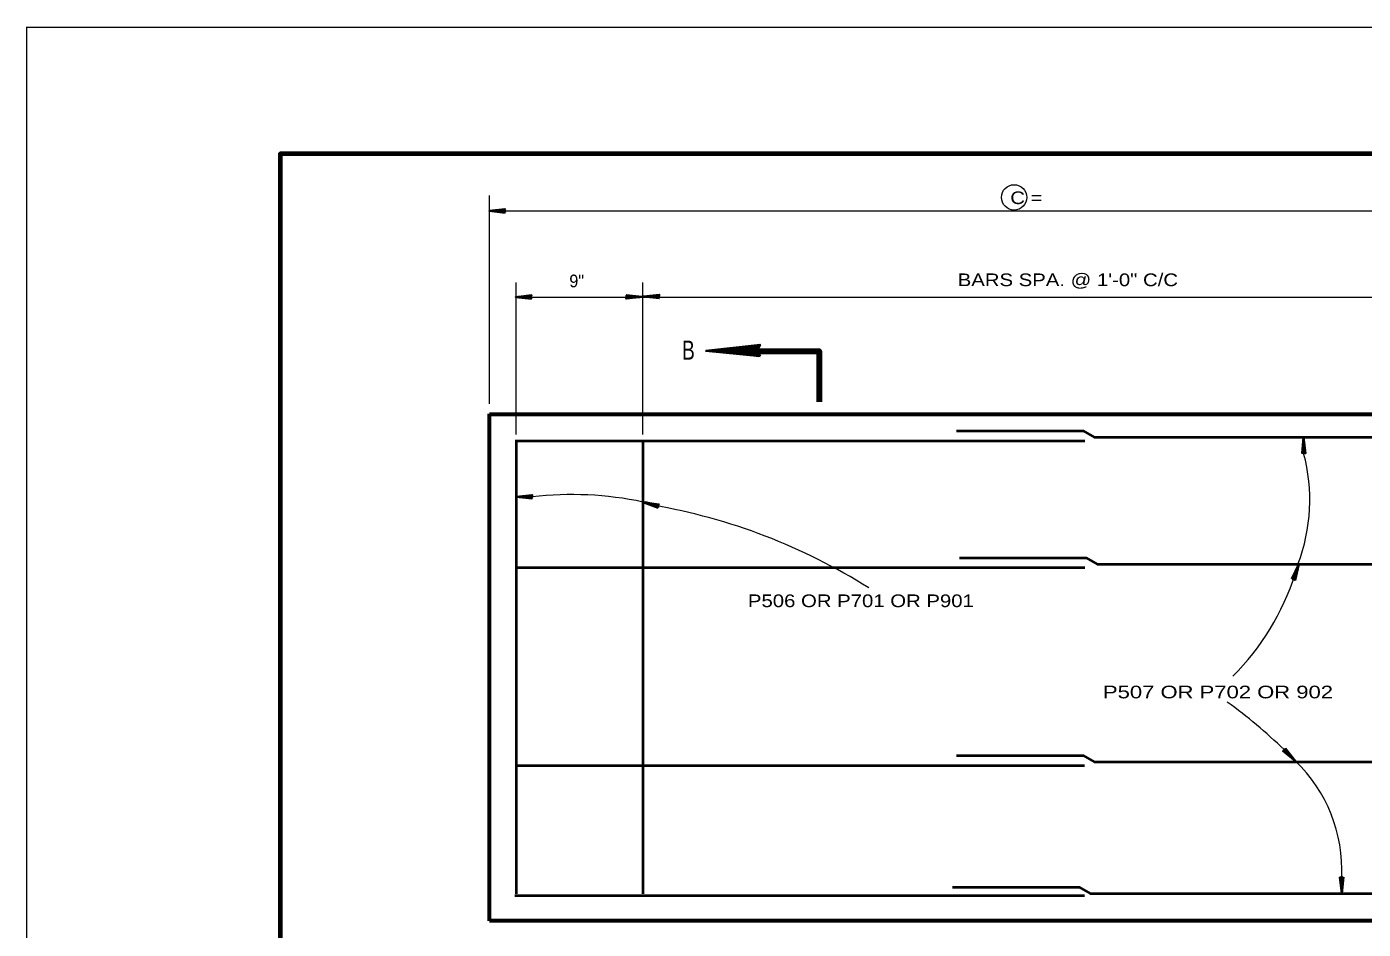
# Model space of a CAD drawing. Extents: x 14.14 to 17.34, y -1.61 to 0.38.
# Drawn here: x 14.143 to 15.022, y -0.211 to 0.382 of the extents above; entities that cross this region are included whole.
import ezdxf
from ezdxf.enums import TextEntityAlignment as Align

# ---------------------------------------------------------------- set-up
doc = ezdxf.new("R2010")
doc.units = 0
doc.header["$LTSCALE"] = 0.0033
doc.layers.add('1', color=7, linetype='Continuous', lineweight=40)

msp = doc.modelspace()

# ---------------------------------------------------------------- linework, layer by layer
at = {"layer": '1', "lineweight": 13}
for p, q in [((14.142583, -1.605917), (14.142583, 0.382333)), ((14.142583, 0.382), (17.339, 0.382)), ((14.447083, 0.134167), (14.447083, 0.271333)), ((14.446917, 0.261167), (15.198083, 0.261167)), ((14.464667, 0.114167), (14.464667, 0.214)), ((14.548, 0.114167), (14.548, 0.214)), ((14.464333, 0.2045), (15.175167, 0.2045))]:
    msp.add_line(p, q, dxfattribs=at)
at = {"layer": '1', "lineweight": 35}
for p, q in [((14.457417, 0.261167), (14.447, 0.261167)), ((14.45725, 0.260417), (14.449417, 0.26125)), ((14.45725, 0.26025), (14.449417, 0.261167)), ((14.45725, 0.26025), (14.449417, 0.261083)), ((14.45725, 0.260167), (14.449417, 0.261)), ((14.45725, 0.260167), (14.449417, 0.261)), ((14.45725, 0.262167), (14.449917, 0.261333)), ((14.45725, 0.262083), (14.45, 0.26125)), ((14.45725, 0.261917), (14.45, 0.261167)), ((14.45725, 0.261833), (14.45, 0.261)), ((14.474833, 0.2045), (14.464417, 0.2045)), ((14.474667, 0.20375), (14.466833, 0.204583)), ((14.474667, 0.203583), (14.466833, 0.2045)), ((14.474667, 0.203583), (14.466833, 0.204417)), ((14.474667, 0.2035), (14.466833, 0.204333)), ((14.474667, 0.2035), (14.466833, 0.204333)), ((14.474667, 0.2055), (14.467333, 0.204667)), ((14.474667, 0.205417), (14.467417, 0.204583)), ((14.474667, 0.20525), (14.467417, 0.2045)), ((14.474667, 0.205167), (14.467417, 0.204333)), ((14.537, 0.204667), (14.547583, 0.204667)), ((14.537167, 0.204), (14.5445, 0.20475)), ((14.53725, 0.205667), (14.545083, 0.20475)), ((14.53725, 0.205667), (14.545083, 0.20475)), ((14.53725, 0.205583), (14.545083, 0.20475)), ((14.53725, 0.2055), (14.545083, 0.204667)), ((14.53725, 0.2055), (14.545083, 0.2045)), ((14.53725, 0.203833), (14.544583, 0.204667)), ((14.53725, 0.20375), (14.544583, 0.2045)), ((14.53725, 0.203583), (14.544583, 0.204417)), ((14.559, 0.204833), (14.548583, 0.204833)), ((14.558833, 0.204083), (14.551, 0.204917)), ((14.558833, 0.203917), (14.551, 0.204833)), ((14.558833, 0.203917), (14.551, 0.20475)), ((14.558833, 0.203833), (14.551, 0.204667)), ((14.558833, 0.203833), (14.551, 0.204667)), ((14.558833, 0.205833), (14.5515, 0.205)), ((14.558833, 0.20575), (14.551583, 0.204917)), ((14.558833, 0.205583), (14.551583, 0.204833)), ((14.558833, 0.2055), (14.551583, 0.204667)), ((14.62525, 0.169083), (14.589583, 0.169083)), ((14.6245, 0.166333), (14.597917, 0.169667)), ((14.6245, 0.166333), (14.597917, 0.169083)), ((14.6245, 0.165667), (14.597917, 0.168917)), ((14.6245, 0.165667), (14.597917, 0.168917)), ((14.6245, 0.166083), (14.597917, 0.168917)), ((14.6245, 0.172833), (14.59975, 0.170083)), ((14.6245, 0.172333), (14.59975, 0.169667)), ((14.6245, 0.171917), (14.59975, 0.169083)), ((14.62475, 0.171333), (14.599833, 0.168917)), ((14.982, 0.101917), (14.982917, 0.10975)), ((14.982, 0.101917), (14.982917, 0.10975)), ((14.982083, 0.101917), (14.982917, 0.10975)), ((14.982167, 0.101917), (14.983, 0.10975)), ((14.982167, 0.101917), (14.983167, 0.10975)), ((14.983667, 0.101833), (14.982917, 0.109167)), ((14.983, 0.101667), (14.983, 0.11225)), ((14.983833, 0.101917), (14.983, 0.10925)), ((14.983917, 0.101917), (14.983167, 0.10925)), ((14.984083, 0.101917), (14.98325, 0.10925)), ((14.475333, 0.073), (14.46475, 0.073)), ((14.475083, 0.072167), (14.46725, 0.073167)), ((14.475083, 0.072167), (14.46725, 0.073)), ((14.475083, 0.072), (14.46725, 0.072917)), ((14.475083, 0.072), (14.46725, 0.072917)), ((14.475083, 0.072083), (14.46725, 0.072917)), ((14.475083, 0.074083), (14.46775, 0.07325)), ((14.475083, 0.073917), (14.46775, 0.073167)), ((14.475083, 0.073833), (14.46775, 0.073)), ((14.475167, 0.073667), (14.467833, 0.072917)), ((14.558417, 0.067), (14.548167, 0.069667)), ((14.558, 0.066167), (14.550583, 0.069083)), ((14.557917, 0.066083), (14.550583, 0.069)), ((14.557917, 0.066083), (14.550583, 0.069)), ((14.557917, 0.066167), (14.550583, 0.069)), ((14.558, 0.066167), (14.550667, 0.06925)), ((14.558417, 0.067917), (14.551083, 0.069083)), ((14.558417, 0.067833), (14.551083, 0.068917)), ((14.558417, 0.068083), (14.551167, 0.069167)), ((14.558417, 0.067667), (14.551167, 0.068833)), ((14.975417, 0.019333), (14.978917, 0.026417)), ((14.975417, 0.019333), (14.978917, 0.026417)), ((14.9755, 0.01925), (14.978917, 0.026417)), ((14.97625, 0.018833), (14.979833, 0.02875)), ((14.975583, 0.01925), (14.979, 0.026333)), ((14.975583, 0.01925), (14.979083, 0.02625)), ((14.976833, 0.018667), (14.97875, 0.025833)), ((14.977083, 0.01875), (14.978833, 0.025917)), ((14.977167, 0.018667), (14.979, 0.025833)), ((14.977333, 0.018583), (14.979083, 0.025833)), ((14.969583, -0.094167), (14.975417, -0.098833)), ((14.96975, -0.094), (14.975583, -0.098583)), ((14.96975, -0.094083), (14.975417, -0.09875)), ((14.969833, -0.093833), (14.975583, -0.0985)), ((14.970167, -0.09325), (14.977583, -0.10075)), ((14.971, -0.09275), (14.976, -0.098917)), ((14.971, -0.092833), (14.975833, -0.099)), ((14.971, -0.092833), (14.975833, -0.099083)), ((14.971083, -0.09275), (14.976, -0.098917)), ((14.971083, -0.09275), (14.976, -0.098917)), ((15.007, -0.1775), (15.007833, -0.184833)), ((15.007167, -0.1775), (15.007917, -0.184833)), ((15.00725, -0.1775), (15.008083, -0.184833)), ((15.007417, -0.177417), (15.008167, -0.18475)), ((15.008917, -0.1775), (15.007917, -0.185333)), ((15.008083, -0.17725), (15.008083, -0.187833)), ((15.008917, -0.1775), (15.008083, -0.185333)), ((15.009083, -0.1775), (15.008167, -0.185333)), ((15.009083, -0.1775), (15.008167, -0.185333)), ((15.009, -0.1775), (15.008167, -0.185333))]:
    msp.add_line(p, q, dxfattribs=at)
at = {"layer": '1', "lineweight": 60}
for p, q in [((14.447083, -0.205833), (14.447083, 0.127667)), ((15.197167, -0.205833), (14.447083, -0.205833))]:
    msp.add_line(p, q, dxfattribs=at)
at = {"layer": '1'}
for p, q in [((14.464, 0.109833), (14.839, 0.109833)), ((14.464667, 0.109833), (14.464667, -0.188083)), ((14.548, 0.109833), (14.548, -0.188083)), ((14.464, 0.0265), (14.839, 0.0265)), ((14.464, 0.0265), (14.839, 0.0265)), ((14.464667, -0.103667), (14.83875, -0.103667)), ((14.463833, -0.189167), (14.838833, -0.189167))]:
    msp.add_line(p, q, dxfattribs=at)
at = {"layer": '1', "lineweight": 70}
msp.add_lwpolyline([(17.256, -1.521417), (17.256, 0.298667), (14.309333, 0.298667), (14.309333, -1.521417)], dxfattribs=at)
at = {"layer": '1', "lineweight": 35}
for points in [[(14.457417, 0.26), (14.447, 0.261167), (14.457417, 0.262333), (14.456833, 0.261167)], [(14.45675, 0.261), (14.452083, 0.261), (14.452083, 0.261083), (14.453, 0.261)], [(14.474833, 0.203333), (14.464417, 0.2045), (14.474833, 0.205667), (14.47425, 0.2045)], [(14.474167, 0.204333), (14.4695, 0.204333), (14.4695, 0.204417), (14.470417, 0.204333)], [(14.537, 0.20575), (14.547583, 0.204667), (14.537, 0.2035), (14.537583, 0.204667)], [(14.53775, 0.20475), (14.542417, 0.204833), (14.542417, 0.20475), (14.5415, 0.20475), (14.53775, 0.204833), (14.54075, 0.204917), (14.537583, 0.205), (14.539833, 0.205083), (14.537583, 0.205167), (14.541083, 0.204917), (14.54575, 0.20475), (14.544833, 0.2045), (14.546083, 0.2045), (14.53775, 0.2045), (14.540167, 0.204333), (14.537583, 0.204333), (14.542917, 0.20475), (14.537583, 0.204083)], [(14.559, 0.203667), (14.548583, 0.204833), (14.559, 0.206), (14.558417, 0.204833)], [(14.558333, 0.204667), (14.553667, 0.204667), (14.553667, 0.20475), (14.554583, 0.204667)], [(14.62525, 0.165583), (14.589583, 0.169083), (14.62525, 0.173083), (14.623333, 0.169083)], [(14.622833, 0.168917), (14.607, 0.168583), (14.607, 0.168917), (14.61, 0.168917), (14.622833, 0.168583), (14.612583, 0.168333), (14.623333, 0.167917), (14.615583, 0.167833), (14.623333, 0.167417), (14.6115, 0.168333), (14.595667, 0.168917), (14.59875, 0.169667), (14.594583, 0.169667), (14.622833, 0.169667), (14.6145, 0.170167), (14.623333, 0.170167), (14.605333, 0.168917), (14.623333, 0.171167)], [(14.981917, 0.101667), (14.983, 0.11225), (14.984167, 0.101667), (14.983, 0.10225)], [(14.982917, 0.102417), (14.982833, 0.107083), (14.982917, 0.107083), (14.982917, 0.106167), (14.982833, 0.102417), (14.98275, 0.105417), (14.982667, 0.10225), (14.982583, 0.1045), (14.9825, 0.10225), (14.98275, 0.10575), (14.982917, 0.110417), (14.983167, 0.1095), (14.983167, 0.11075), (14.983167, 0.102417), (14.983333, 0.104833), (14.983333, 0.10225), (14.982917, 0.107583), (14.983583, 0.10225)], [(14.475333, 0.071917), (14.46475, 0.073), (14.475333, 0.074167), (14.47475, 0.073)], [(14.474583, 0.072917), (14.469917, 0.072833), (14.469917, 0.072917), (14.470833, 0.072917), (14.474583, 0.072833), (14.471583, 0.07275), (14.47475, 0.072667), (14.4725, 0.072583), (14.47475, 0.0725), (14.47125, 0.07275), (14.466583, 0.072917), (14.4675, 0.073167), (14.46625, 0.073167), (14.474583, 0.073167), (14.472167, 0.073333), (14.47475, 0.073333), (14.469417, 0.072917), (14.47475, 0.073583)], [(14.558167, 0.065917), (14.548167, 0.069667), (14.558667, 0.068083), (14.557833, 0.067083)], [(14.557667, 0.067083), (14.553167, 0.068167), (14.553167, 0.06825), (14.554, 0.068083), (14.557667, 0.067), (14.554833, 0.067667), (14.55775, 0.066833), (14.555583, 0.06725), (14.55775, 0.066667), (14.554417, 0.06775), (14.55, 0.069167), (14.550917, 0.069167), (14.54975, 0.0695), (14.557667, 0.067333), (14.555417, 0.068083), (14.557917, 0.067417), (14.552667, 0.068417), (14.558083, 0.06775)], [(14.975167, 0.019167), (14.979833, 0.02875), (14.977333, 0.018333), (14.976417, 0.01925)], [(14.976417, 0.0195), (14.977917, 0.023833), (14.978, 0.023833), (14.97775, 0.023083), (14.976333, 0.0195), (14.97725, 0.022333), (14.976083, 0.019417), (14.97675, 0.021583), (14.975917, 0.0195), (14.977417, 0.022667), (14.979083, 0.027), (14.979, 0.026083), (14.9795, 0.02725), (14.976667, 0.019417), (14.977583, 0.021583), (14.97675, 0.019167), (14.978167, 0.024333), (14.977, 0.019083)], [(14.971, -0.0925), (14.977583, -0.10075), (14.969333, -0.094083), (14.970583, -0.09375)], [(14.970833, -0.09375), (14.974167, -0.097), (14.974083, -0.097), (14.973417, -0.096417), (14.970833, -0.093667), (14.973, -0.09575), (14.970833, -0.093417), (14.972417, -0.095), (14.971, -0.093333), (14.973167, -0.096), (14.976417, -0.099417), (14.975667, -0.099), (14.976417, -0.099833), (14.970583, -0.093917), (14.97225, -0.09575), (14.970417, -0.093917), (14.974417, -0.097417), (14.97025, -0.094167)], [(15.009167, -0.17725), (15.008083, -0.187833), (15.006917, -0.17725), (15.008083, -0.177833)], [(15.008167, -0.178), (15.00825, -0.182667), (15.008167, -0.182667), (15.008167, -0.18175), (15.00825, -0.178), (15.008333, -0.181), (15.008417, -0.177833), (15.0085, -0.180083), (15.008583, -0.177833), (15.008333, -0.181333), (15.008167, -0.186), (15.007917, -0.185083), (15.007917, -0.186333), (15.007917, -0.178), (15.00775, -0.180417), (15.00775, -0.177833), (15.008167, -0.183167), (15.0075, -0.177833)]]:
    msp.add_lwpolyline(points, close=True, dxfattribs=at)
for points in [[(14.45675, 0.261), (14.45375, 0.260833), (14.456833, 0.260833), (14.454667, 0.26075), (14.457, 0.260583), (14.453417, 0.260917), (14.44875, 0.261083), (14.449667, 0.261333), (14.448417, 0.26125), (14.45675, 0.26125), (14.454333, 0.261417), (14.456833, 0.261417), (14.451583, 0.261083), (14.456917, 0.261667), (14.456667, 0.261083), (14.457167, 0.260333), (14.456917, 0.2605), (14.456667, 0.260917), (14.456417, 0.26075), (14.456667, 0.260417), (14.45675, 0.261167), (14.457, 0.261667), (14.45725, 0.262167)], [(14.474167, 0.204333), (14.471167, 0.204167), (14.47425, 0.204167), (14.472083, 0.204083), (14.474417, 0.203917), (14.470833, 0.20425), (14.466167, 0.204417), (14.467083, 0.204667), (14.465833, 0.204583), (14.474167, 0.204583), (14.47175, 0.20475), (14.47425, 0.20475), (14.469, 0.204417), (14.474333, 0.205), (14.474083, 0.204417), (14.474583, 0.203667), (14.474333, 0.203833), (14.474083, 0.20425), (14.473833, 0.204083), (14.474083, 0.20375), (14.474167, 0.2045), (14.474417, 0.205), (14.474667, 0.2055)], [(14.53775, 0.20475), (14.537333, 0.2055), (14.537583, 0.20525), (14.53775, 0.204917), (14.538, 0.205), (14.537833, 0.205333), (14.537667, 0.204583), (14.5375, 0.204083), (14.53725, 0.203667)], [(14.558333, 0.204667), (14.555333, 0.2045), (14.558417, 0.2045), (14.55625, 0.204417), (14.558583, 0.20425), (14.555, 0.204583), (14.550333, 0.20475), (14.55125, 0.205), (14.55, 0.204917), (14.558333, 0.204917), (14.555917, 0.205083), (14.558417, 0.205083), (14.553167, 0.20475), (14.5585, 0.205333), (14.55825, 0.20475), (14.55875, 0.204), (14.5585, 0.204167), (14.55825, 0.204583), (14.558, 0.204417), (14.55825, 0.204083), (14.558333, 0.204833), (14.558583, 0.205333), (14.558833, 0.205833)], [(14.622833, 0.168917), (14.624083, 0.166333), (14.623333, 0.167167), (14.622833, 0.168333), (14.621833, 0.167917), (14.6225, 0.166833), (14.623, 0.169417), (14.623583, 0.171167), (14.6245, 0.172417)], [(14.982917, 0.102417), (14.982167, 0.102), (14.982417, 0.10225), (14.98275, 0.102417), (14.982667, 0.102667), (14.982333, 0.1025), (14.983083, 0.102333), (14.983583, 0.102167), (14.984, 0.101917)], [(14.474583, 0.072917), (14.475, 0.072167), (14.47475, 0.072417), (14.474583, 0.07275), (14.474333, 0.072667), (14.4745, 0.072333), (14.474667, 0.073083), (14.474833, 0.073583), (14.475083, 0.074)], [(14.557667, 0.067083), (14.557917, 0.06625), (14.55775, 0.066583), (14.557667, 0.066917), (14.557417, 0.066917), (14.557417, 0.066583), (14.557833, 0.067167), (14.558083, 0.06775), (14.5585, 0.068)], [(14.976417, 0.0195), (14.975583, 0.019333), (14.975833, 0.0195), (14.97625, 0.019583), (14.97625, 0.019833), (14.975833, 0.01975), (14.976583, 0.019333), (14.977, 0.019), (14.97725, 0.018583)], [(14.970833, -0.09375), (14.971, -0.092917), (14.971, -0.09325), (14.970917, -0.093583), (14.971167, -0.09375), (14.97125, -0.093333), (14.970583, -0.09375), (14.970167, -0.094), (14.969583, -0.094167)], [(15.008167, -0.178), (15.008917, -0.177583), (15.008667, -0.177833), (15.008333, -0.178), (15.008417, -0.17825), (15.00875, -0.178083), (15.008, -0.177917), (15.0075, -0.17775), (15.007083, -0.1775)]]:
    msp.add_lwpolyline(points, dxfattribs=at)
at = {"layer": '1', "lineweight": 90}
msp.add_lwpolyline([(14.6225, 0.168917), (14.664167, 0.168917), (14.664167, 0.1355)], dxfattribs=at)
at = {"layer": '1', "lineweight": 60}
msp.add_lwpolyline([(14.447083, 0.1275), (14.664167, 0.1275), (15.196917, 0.1275)], dxfattribs=at)
at = {"layer": '1'}
for points in [[(14.754583, 0.116417), (14.837917, 0.116417), (14.845167, 0.11225), (15.179167, 0.11225)], [(14.756583, 0.033), (14.839917, 0.033), (14.847167, 0.028833), (15.1785, 0.028833)], [(14.754583, -0.097083), (14.837917, -0.097083), (14.845167, -0.10125), (15.178167, -0.10125)], [(14.751917, -0.18375), (14.83525, -0.18375), (14.8425, -0.187917), (15.179417, -0.187917)]]:
    msp.add_lwpolyline(points, dxfattribs=at)
at = {"layer": '1', "lineweight": 13}
msp.add_circle((14.792417, 0.270083), 0.008333, dxfattribs=at)
for centre, radius, start, end in [((14.869384, 0.071003), 0.117681, 339.00173, 15.10346), ((14.501658, -0.149168), 0.223722, 78.00163, 96.75756), ((14.48843, -0.318134), 0.391353, 57.83856, 80.21788), ((14.81805, 0.073393), 0.167355, 314.97339, 342.20777), ((14.717236, -0.35728), 0.365631, 46.22994, 53.88334), ((14.908674, -0.172554), 0.09952, 357.29531, 46.17832)]:
    msp.add_arc(centre, radius, start, end, dxfattribs=at)

# ---------------------------------------------------------------- texts
at = {"layer": '1'}
for s, height, width, p in [('C =      ', 0.008334, 1.2, (14.789917, 0.265667)), ('BARS SPA. @ 1\'-0" C/C', 0.008334, 1.2, (14.755333, 0.211667)), ('B', 0.0125, 0.75, (14.573917, 0.163333)), ('P506 OR P701 OR P901', 0.008334, 1.2, (14.61725, 0.0005)), ('P507 OR P702 OR 902', 0.008334, 1.3, (14.850917, -0.0595))]:
    msp.add_text(s, height=height, dxfattribs=dict(at, width=width)).set_placement(p)
at = {"layer": '1', "width": 0.95}
msp.add_text('9"', height=0.008334, dxfattribs=at).set_placement((14.504542, 0.210917), align=Align.CENTER)

doc.saveas('drawing.dxf')
